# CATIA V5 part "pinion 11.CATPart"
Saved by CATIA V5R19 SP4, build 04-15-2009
Part number: pinion 11
Bounding box of the stored display mesh (mm): x 0 to 22.15, y -45.856 to 45.856, z -45.66 to 45.66
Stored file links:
  G:\EU_thinkMotion\CFAO_2010\MMS_groupe1\MMS_groupe1\A reprendre\OK\rdeneffle\pinion 11.CATPart
  G:\EU_thinkMotion\CFAO_2010\MMS_groupe1\MMS_groupe1\A reprendre\OK\rdeneffle\pinion 2.CATPart
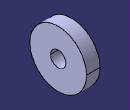
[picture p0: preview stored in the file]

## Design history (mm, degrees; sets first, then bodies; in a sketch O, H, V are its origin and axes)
Parameters
  `rayon interieur.1` = 12.5 mm
  `rayon extérieur.1` = 45.856 mm
Body1 (main body)
Body2
  Sketch1 on yz-plane, origin (0, 0, 0), H (0, 1, 0), V (0, 0, 1)
    circle A1 centre (0, 0) radius 12.5
    circle A2 centre (0, 0) radius 45.856
    radius A2 = 45.856 {= `rayon extérieur.1`}
    radius A1 = 12.5 {= `rayon interieur.1`}
  Pad1: profile Sketch1, direction (1, 0, 0), length 22.15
